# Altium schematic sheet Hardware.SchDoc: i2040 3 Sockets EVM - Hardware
size 431 x 279 mm; Date: Not shown in title block; ApprovedBy: Not shown in title block; CheckedBy: Not shown in title block; Author: Not shown in title block; CompanyName: Texas Instruments; DrawnBy: Mars Leung; Engineer: Mars Leung; Organization: Not shown in title block; Address1: Not shown in title block; Address2: Not shown in title block; Address3: Not shown in title block; Address4: Not shown in title block; DocumentNumber: 1; Revision: Use project parameter SCH_Rev; SheetNumber: 2; SheetTotal: 3; PageSetup: Record=PageOptions|CenterHorizontal=True|CenterVertical=True|PrintScale=1.00|XCorrection=1.00|YCorrection=1.00|PrintKind=0|BorderSize=5000000|LeftOffset=0|BottomOffset=0|Orientation=2|PaperLength=1000|PaperWidth=1000|Scale=100|PaperSource=15|PrintQuality=600|MediaType=1|DitherType=10|PaperKind=Letter|PrintScaleMode=1
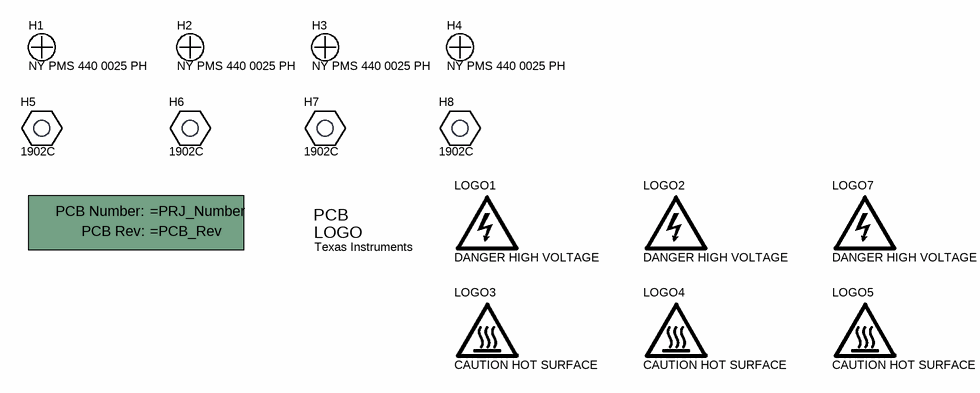
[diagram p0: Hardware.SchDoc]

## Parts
!PCB  Printed Circuit Board  (value not drawn)  (mechanical)
H1  NY PMS 440 0025 PH  [NY PMS 440 0025 PH]
H2  NY PMS 440 0025 PH  [NY PMS 440 0025 PH]
H3  NY PMS 440 0025 PH  [NY PMS 440 0025 PH]
H4  NY PMS 440 0025 PH  [NY PMS 440 0025 PH]
H5  1902C  [Keystone_1902C]
H6  1902C  [Keystone_1902C]
H7  1902C  [Keystone_1902C]
H8  1902C  [Keystone_1902C]
LOGO1  DANGER HIGH VOLTAGE  [IEC_HighVoltage_Small]  (no BOM)
LOGO2  DANGER HIGH VOLTAGE  [IEC_HighVoltage_Small]  (no BOM)
LOGO3  CAUTION HOT SURFACE  [IEC_HotSurface_Small]  (no BOM)
LOGO4  CAUTION HOT SURFACE  [IEC_HotSurface_Small]  (no BOM)
LOGO5  CAUTION HOT SURFACE  [IEC_HotSurface_Small]  (no BOM)
Logo6  Texas Instruments  [TI_Stacked_SolderMask_Medium]  (no BOM)
LOGO7  DANGER HIGH VOLTAGE  [IEC_HighVoltage_Small]  (no BOM)

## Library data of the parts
!PCB = PCB: Manufacturer: Any; SymbolCreator: a0412235
H1-H4 = NY PMS 440 0025 PH: Machine Screw, Round, #4-40 x 1/4, Nylon, Philips panhead; Manufacturer: B&F Fastener Supply; CompType: Hardware; SymbolCreator: codlsc; U/M: EA
H5-H8 = 1902C: Standoff, Hex, 0.5"L #4-40 Nylon; Manufacturer: Keystone; CompType: Hardware
LOGO1 LOGO2 LOGO7 = IEC_HighVoltage: IEC 61010-1 High Voltage Warning; SymbolCreator: a0412235
LOGO3-LOGO5 = IEC_HotSurface: IEC 61010-1 Hot Surface Warning; SymbolCreator: a0412235
Logo6 = TI_Logo: Texas Instrument Corporate Signature; SymbolCreator: a0412235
